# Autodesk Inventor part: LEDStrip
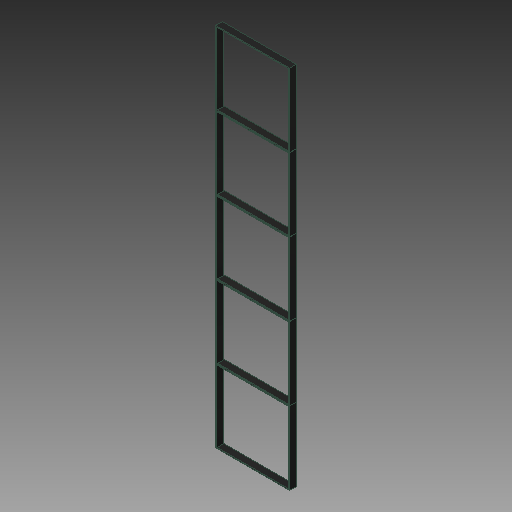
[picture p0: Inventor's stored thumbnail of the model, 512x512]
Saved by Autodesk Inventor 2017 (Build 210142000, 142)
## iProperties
Created: 2017-05
Part Number: LEDStrip
Material: Generic
Document SubType Name: Modeling
Designer: Savy
Density: 1 g/cm^3
Appearance: Default
Mass: 30.6781 g
Surface Area: 492.131 cm^2
Volume: 30.6781 cm^3
Author: Savy
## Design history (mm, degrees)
feature "SOLID1"
body "Solid1"
